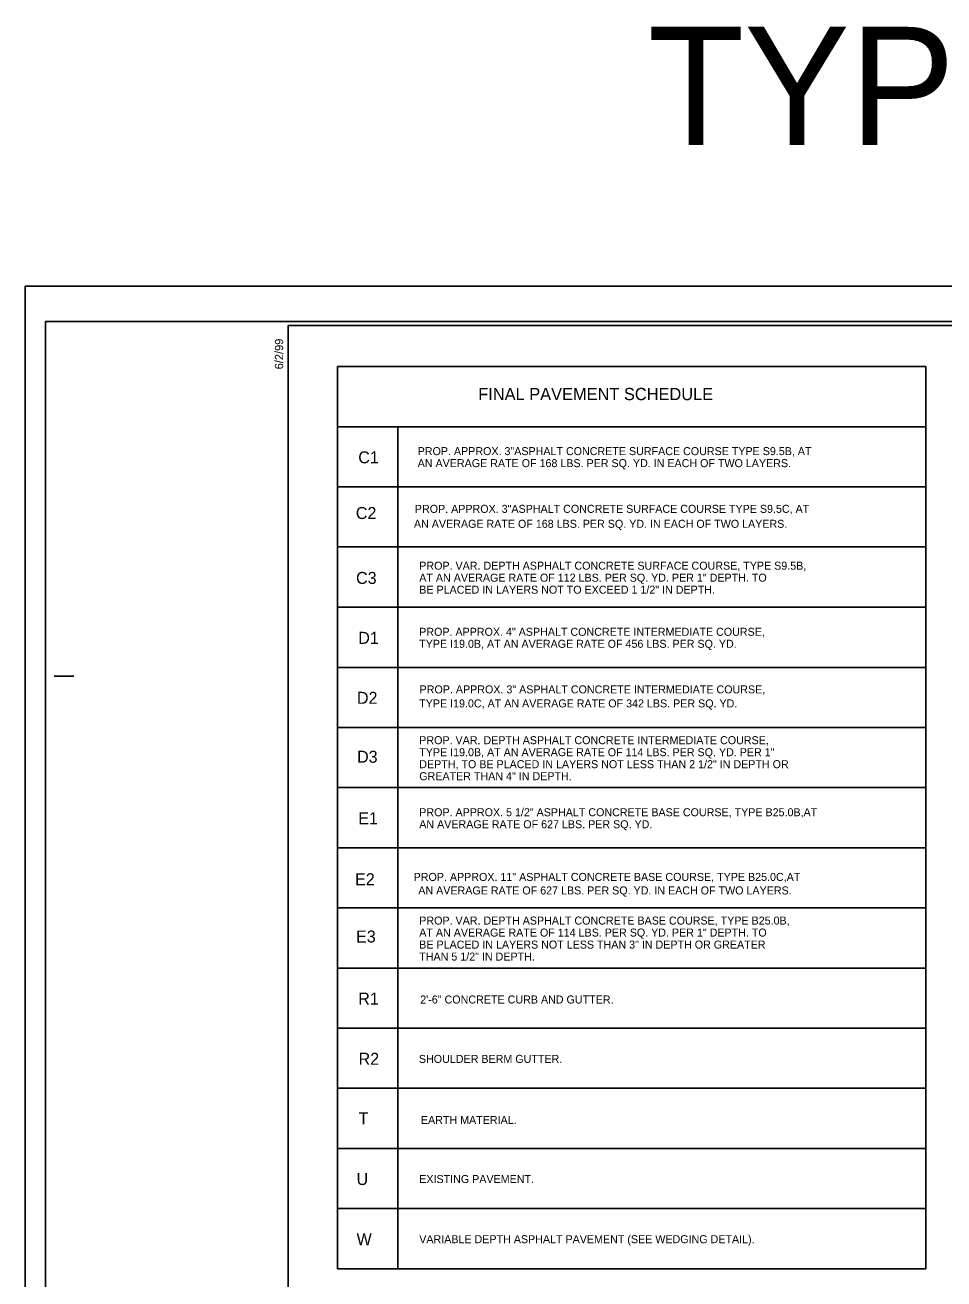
# Model space of a CAD drawing. Extents: x 981824 to 982276, y 44828 to 45204.
# Drawn here: x 982094.4 to 982141, y 45127.5 to 45191.2 of the extents above; entities that cross this region are included whole.
import ezdxf

# ---------------------------------------------------------------- set-up
doc = ezdxf.new("R2010")
doc.units = 0
for name, color, linetype in [('Default', 7, 'Continuous'), ('Old_Level_1', 7, 'Continuous'), ('Old_Level_18', 7, 'Continuous'), ('Old_Level_19', 7, 'Continuous'), ('Old_Level_21', 7, 'Continuous'), ('Old_Level_3', 7, 'Continuous'), ('Old_Level_41', 7, 'Continuous'), ('Old_Level_50', 7, 'Continuous'), ('Old_Level_51', 7, 'Continuous'), ('Prop Roadway Profile Bench Mark Info Text', 7, 'Continuous')]:
    doc.layers.add(name, color=color, linetype=linetype)

msp = doc.modelspace()

# ---------------------------------------------------------------- linework, layer by layer
at = {"layer": 'Default'}
msp.add_line((982110.236, 45128.067), (982110.236, 45128.067), dxfattribs=at)
at = {"layer": 'Old_Level_18'}
msp.add_lwpolyline([(982227.72, 45175.969), (982107.72, 45175.969), (982107.72, 45091.969), (982227.72, 45091.969)], close=True, dxfattribs=at)
at = {"layer": 'Old_Level_19'}
for points in [[(982113.292, 45167.78), (982110.236, 45167.78), (982110.236, 45170.834), (982140.109, 45170.834), (982140.109, 45167.78), (982113.292, 45167.78), (982113.292, 45170.834)], [(982113.292, 45164.726), (982110.236, 45164.726), (982110.236, 45167.78), (982140.107, 45167.78), (982140.107, 45164.726), (982113.292, 45164.726), (982113.292, 45167.78)], [(982113.292, 45161.672), (982110.236, 45161.672), (982110.236, 45164.726), (982140.107, 45164.726), (982140.107, 45161.672), (982113.292, 45161.672), (982113.292, 45164.726)], [(982113.292, 45158.611), (982110.236, 45158.611), (982110.236, 45161.668), (982140.107, 45161.668), (982140.107, 45158.611), (982113.292, 45158.611), (982113.292, 45161.668)], [(982113.292, 45155.557), (982110.236, 45155.557), (982110.236, 45158.611), (982140.107, 45158.611), (982140.107, 45155.557), (982113.292, 45155.557), (982113.292, 45158.611)], [(982113.292, 45152.503), (982110.236, 45152.503), (982110.236, 45155.557), (982140.107, 45155.557), (982140.107, 45152.503), (982113.292, 45152.503), (982113.292, 45155.557)], [(982113.292, 45149.448), (982110.236, 45149.448), (982110.236, 45152.503), (982140.107, 45152.503), (982140.107, 45149.448), (982113.292, 45149.448), (982113.292, 45152.503)], [(982113.292, 45146.394), (982110.236, 45146.394), (982110.236, 45149.448), (982140.107, 45149.448), (982140.107, 45146.394), (982113.292, 45146.394), (982113.292, 45149.448)], [(982113.292, 45143.34), (982110.236, 45143.34), (982110.236, 45146.394), (982140.107, 45146.394), (982140.107, 45143.34), (982113.292, 45143.34), (982113.292, 45146.394)], [(982113.292, 45140.286), (982110.236, 45140.286), (982110.236, 45143.34), (982140.107, 45143.34), (982140.107, 45140.286), (982113.292, 45140.286), (982113.292, 45143.34)], [(982113.292, 45137.232), (982110.236, 45137.232), (982110.236, 45140.286), (982140.107, 45140.286), (982140.107, 45137.232), (982113.292, 45137.232), (982113.292, 45140.286)], [(982113.292, 45134.178), (982110.236, 45134.178), (982110.236, 45137.232), (982140.107, 45137.232), (982140.107, 45134.178), (982113.292, 45134.178), (982113.292, 45137.232)], [(982113.292, 45131.124), (982110.236, 45131.124), (982110.236, 45134.178), (982140.107, 45134.178), (982140.107, 45131.124), (982113.292, 45131.124), (982113.292, 45134.178)], [(982113.292, 45128.067), (982110.236, 45128.067), (982110.236, 45131.124), (982140.107, 45131.124), (982140.107, 45128.067), (982113.292, 45128.067), (982113.292, 45131.124)]]:
    msp.add_lwpolyline(points, dxfattribs=at)
at = {"layer": 'Old_Level_41'}
msp.add_line((982095.84, 45158.169), (982096.84, 45158.169), dxfattribs=at)
at = {"layer": 'Old_Level_50'}
msp.add_lwpolyline([(982228.72, 45176.173), (982095.4, 45176.173), (982095.4, 45091.765), (982228.72, 45091.765)], close=True, dxfattribs=at)
at = {"layer": 'Old_Level_51'}
msp.add_lwpolyline([(982229.08, 45177.969), (982094.36, 45177.969), (982094.36, 45089.969), (982229.08, 45089.969)], close=True, dxfattribs=at)
at = {"layer": 'Prop Roadway Profile Bench Mark Info Text'}
msp.add_lwpolyline([(982110.236, 45173.89), (982140.109, 45173.89), (982140.109, 45170.834), (982110.236, 45170.834)], close=True, dxfattribs=at)

# ---------------------------------------------------------------- texts
at = {"layer": 'Old_Level_1'}
msp.add_text('TYPICAL SECTIONS', height=6, dxfattribs=at).set_placement((982125.989, 45185.148))
at = {"layer": 'Old_Level_21'}
for s, height, p in [('PROP. APPROX. 3"ASPHALT CONCRETE SURFACE COURSE TYPE S9.5B, AT', 0.40637, (982114.301, 45169.393)), ('C1', 0.6099, (982111.284, 45168.975)), ('AN AVERAGE RATE OF 168 LBS. PER SQ. YD. IN EACH OF TWO LAYERS.', 0.40637, (982114.301, 45168.782)), ('C2', 0.6099, (982111.159, 45166.147)), ('PROP. APPROX. 3"ASPHALT CONCRETE SURFACE COURSE TYPE S9.5C, AT', 0.40637, (982114.158, 45166.461)), ('AN AVERAGE RATE OF 168 LBS. PER SQ. YD. IN EACH OF TWO LAYERS.', 0.40637, (982114.111, 45165.701)), ('PROP. VAR. DEPTH ASPHALT CONCRETE SURFACE COURSE, TYPE S9.5B,', 0.40637, (982114.381, 45163.573)), ('C3', 0.6099, (982111.173, 45162.849)), ('AT AN AVERAGE RATE OF 112 LBS. PER SQ. YD. PER 1" DEPTH. TO', 0.40637, (982114.381, 45162.964)), ('BE PLACED IN LAYERS NOT TO EXCEED 1 1/2" IN DEPTH.', 0.40637, (982114.381, 45162.354)), ('D1', 0.6099, (982111.284, 45159.807)), ('PROP. APPROX. 4" ASPHALT CONCRETE INTERMEDIATE COURSE,', 0.40637, (982114.378, 45160.215)), ('TYPE I19.0B, AT AN AVERAGE RATE OF 456 LBS. PER SQ. YD.', 0.40637, (982114.378, 45159.606)), ('PROP. APPROX. 3" ASPHALT CONCRETE INTERMEDIATE COURSE,', 0.40637, (982114.398, 45157.29)), ('D2', 0.6099, (982111.216, 45156.76)), ('TYPE I19.0C, AT AN AVERAGE RATE OF 342 LBS. PER SQ. YD.', 0.40637, (982114.378, 45156.578)), ('PROP. VAR. DEPTH ASPHALT CONCRETE INTERMEDIATE COURSE,', 0.40637, (982114.381, 45154.71)), ('D3', 0.6099, (982111.222, 45153.766)), ('TYPE I19.0B, AT AN AVERAGE RATE OF 114 LBS. PER SQ. YD. PER 1" ', 0.40637, (982114.381, 45154.1)), ('DEPTH, TO BE PLACED IN LAYERS NOT LESS THAN 2 1/2" IN DEPTH OR', 0.40637, (982114.381, 45153.491)), ('GREATER THAN 4" IN DEPTH.', 0.40637, (982114.381, 45152.882)), ('E1', 0.6099, (982111.284, 45150.642)), ('PROP. APPROX. 5 1/2" ASPHALT CONCRETE BASE COURSE, TYPE B25.0B,AT', 0.40637, (982114.381, 45151.049)), ('AN AVERAGE RATE OF 627 LBS. PER SQ. YD. ', 0.40637, (982114.381, 45150.439)), ('E2', 0.6099, (982111.12, 45147.544)), ('PROP. APPROX. 11" ASPHALT CONCRETE BASE COURSE, TYPE B25.0C,AT', 0.40637, (982114.096, 45147.764)), ('AN AVERAGE RATE OF 627 LBS. PER SQ. YD. IN EACH OF TWO LAYERS.', 0.40637, (982114.333, 45147.078)), ('PROP. VAR. DEPTH ASPHALT CONCRETE BASE COURSE, TYPE B25.0B,', 0.40637, (982114.381, 45145.547)), ('E3', 0.6099, (982111.173, 45144.636)), ('AT AN AVERAGE RATE OF 114 LBS. PER SQ. YD. PER 1" DEPTH. TO', 0.40637, (982114.381, 45144.938)), ('BE PLACED IN LAYERS NOT LESS THAN 3" IN DEPTH OR GREATER', 0.40637, (982114.381, 45144.327)), ('THAN 5 1/2" IN DEPTH.', 0.40637, (982114.381, 45143.718)), ('R1', 0.6105, (982111.283, 45141.48)), ('2\'-6" CONCRETE CURB AND GUTTER.', 0.40676, (982114.432, 45141.538)), ('R2', 0.6105, (982111.3, 45138.424)), ('SHOULDER BERM GUTTER.', 0.40676, (982114.362, 45138.52)), ('T ', 0.6099, (982111.297, 45135.395)), ('EARTH MATERIAL.', 0.40637, (982114.465, 45135.417)), ('U ', 0.6099, (982111.198, 45132.318)), ('EXISTING PAVEMENT.', 0.40637, (982114.381, 45132.418)), ('W ', 0.6099, (982111.198, 45129.262)), ('VARIABLE DEPTH ASPHALT PAVEMENT (SEE WEDGING DETAIL).', 0.40637, (982114.381, 45129.363))]:
    msp.add_text(s, height=height, dxfattribs=at).set_placement(p)
at = {"layer": 'Old_Level_3'}
msp.add_text('FINAL PAVEMENT SCHEDULE', height=0.62231, dxfattribs=at).set_placement((982117.378, 45172.185))
at = {"layer": 'Old_Level_41'}
msp.add_text('6/2/99', height=0.42, rotation=90, dxfattribs=at).set_placement((982107.468, 45173.749))

doc.saveas('drawing.dxf')
